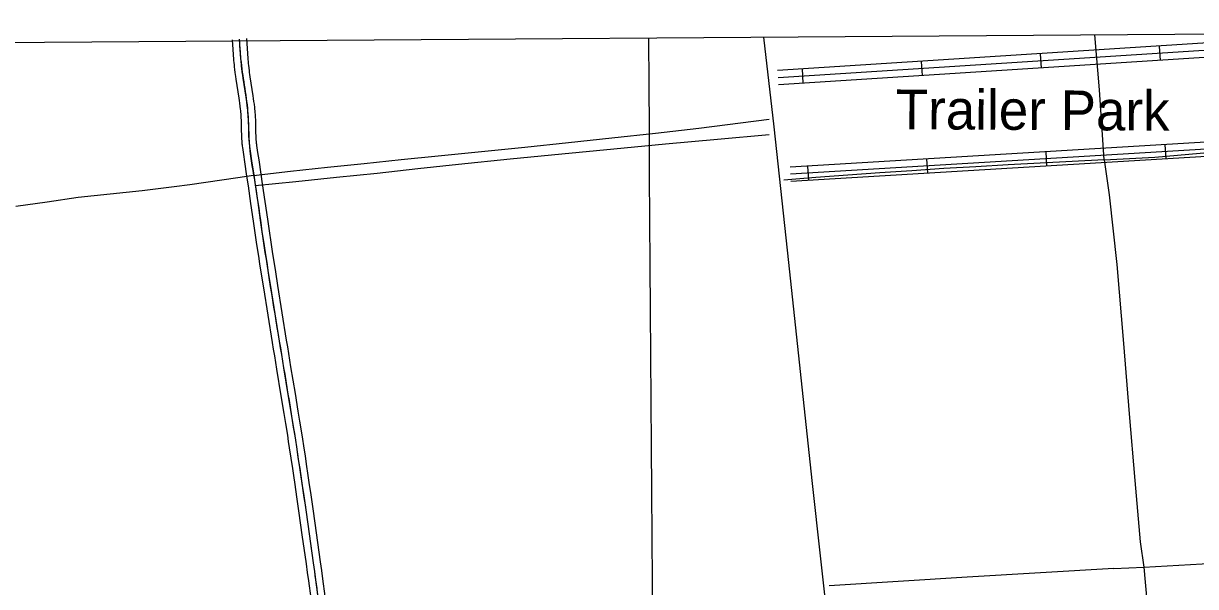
# Model space of a CAD drawing. Extents: x 3508733 to 3546731, y 546897 to 572481.
# Drawn here: x 3516762 to 3519217, y 569367 to 570545 of the extents above; entities that cross this region are included whole.
import ezdxf

# ---------------------------------------------------------------- set-up
doc = ezdxf.new("R2010")
doc.units = 0
for name, color, linetype in [('V-BLDG-IDEN', 7, 'Continuous'), ('V-DTCH-CNTR', 7, 'Continuous'), ('V-GRID-FRAM', 7, 'Continuous'), ('V-GRID-MAJR', 7, 'Continuous'), ('V-ROAD-CNTR', 7, 'Continuous'), ('V-TOPO-SHOR', 7, 'Continuous')]:
    doc.layers.add(name, color=color, linetype=linetype)

msp = doc.modelspace()

# ---------------------------------------------------------------- linework, layer by layer
at = {"layer": 'V-DTCH-CNTR'}
for points in [[(3519026.147, 570259.807), (3519015.829, 570405.975), (3519006.211868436, 570521.2976405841)], [(3517244.149, 570227.107), (3517321.3710000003, 570235.645), (3517398.613, 570243.984), (3517475.878, 570252.129), (3517553.166, 570260.073), (3517630.471, 570267.821), (3517721.577, 570276.832), (3517812.653, 570286.106), (3517903.705, 570295.6410000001), (3517994.7290000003, 570305.441), (3518085.721, 570315.501), (3518176.687, 570325.8250000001), (3518324.002, 570344.893)], [(3518324.387, 570312.191), (3518215.792, 570302.311), (3518107.215, 570292.231), (3517998.659, 570281.9500000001), (3517890.119, 570271.469), (3517781.599, 570260.784), (3517673.1010000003, 570249.899), (3517587.977, 570240.527), (3517502.8340000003, 570231.356), (3517417.668, 570222.388), (3517332.481, 570213.623), (3517247.274, 570205.06)], [(3519026.147, 570259.807), (3519132.288, 570265.251), (3519274.536, 570277.596), (3519400.435, 570284.74), (3519509.528, 570289.649), (3519634.452, 570297.794), (3519703.076, 570303.182)], [(3519026.147, 570259.807), (3518958.935, 570256.506), (3518891.736, 570252.996), (3518824.548, 570249.272), (3518757.3710000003, 570245.34), (3518690.207, 570241.1950000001), (3518623.055, 570236.843), (3518555.92, 570232.276), (3518488.798, 570227.502), (3518421.6920000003, 570222.515), (3518354.6010000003, 570217.319)], [(3519026.147, 570259.807), (3519036.4790000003, 570186.159), (3519052.73, 570040.897), (3519066.722, 569874.9450000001), (3519078.018, 569728.269), (3519090.398, 569588.487), (3519101.454, 569460.069), (3519108.699, 569407.409), (3519119.0270000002, 569297.7490000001), (3519134.738, 569149.04), (3519145.529, 569001.385), (3519159.705, 568848.752), (3519174.594, 568676.3740000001), (3519184.137, 568545.51), (3519197.224, 568385.492), (3519208.623, 568246.216), (3519211.1920000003, 568179.8690000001)], [(3517244.149, 570227.107), (3517210.857, 570221.895), (3517177.534, 570216.887), (3517144.18, 570212.085), (3517110.798, 570207.483), (3517077.389, 570203.086), (3517043.953, 570198.892), (3517010.4930000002, 570194.9), (3516977.0100000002, 570191.115), (3516943.503, 570187.533), (3516909.977, 570184.154), (3516876.429, 570180.982), (3516811.417, 570171.307), (3516746.3680000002, 570161.866)], [(3519046.498, 569404.321), (3519108.699, 569407.409), (3519231.137, 569414.108), (3519355.088, 569423.252), (3519476.623, 569435.883), (3519610.486, 569448.345), (3519731.472, 569457.036)], [(3519046.498, 569404.321), (3518738.9450000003, 569386.243), (3518450.011, 569367.838)]]:
    msp.add_lwpolyline(points, dxfattribs=at)
at = {"layer": 'V-GRID-FRAM'}
msp.add_lwpolyline([(3512799.986, 570478.871), (3544431.278, 570695.107), (3544563.5130000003, 552512.398), (3512916.353, 552296.053), (3512799.986, 570478.871)], dxfattribs=at)
at = {"layer": 'V-GRID-MAJR'}
msp.add_spline([(3518190.879, 552332.11), (3518151.221, 558391.11), (3518111.551, 564452.0430000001), (3518071.881, 570512.993), (3518071.8680000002, 570514.91)], degree=3, dxfattribs=at)
at = {"layer": 'V-ROAD-CNTR'}
for p, q in [((3519144.061673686, 570467.8630378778), (3519142.1416775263, 570497.8009780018)), ((3518645.0866716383, 570435.8711018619), (3518643.167675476, 570465.8100419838)), ((3518894.5741726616, 570451.86706987), (3518892.6541765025, 570481.8060099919)), ((3518395.5991706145, 570419.876133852), (3518393.680174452, 570449.8140739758)), ((3518906.0561496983, 570246.7004802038), (3518904.258153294, 570276.646420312)), ((3519155.606650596, 570261.683450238), (3519153.808654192, 570291.6293903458)), ((3518406.9561479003, 570216.735540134), (3518405.158151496, 570246.681480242)), ((3518656.5056488, 570231.7185101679), (3518654.707652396, 570261.664450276))]:
    msp.add_line(p, q, dxfattribs=at)
for points in [[(3519623.991713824, 570528.6939162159), (3518341.754278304, 570446.4850806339)], [(3519691.97357786, 570518.0219375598), (3518342.7142763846, 570431.5161105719)], [(3517265.371431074, 569992.0659894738), (3517260.8234401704, 570020.723932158), (3517257.444446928, 570042.235889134), (3517254.93345195, 570058.3828568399), (3517251.215459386, 570082.6048083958), (3517247.561466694, 570106.8477599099), (3517243.925473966, 570131.490710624), (3517238.5704846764, 570168.4266367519), (3517233.226495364, 570205.3275629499), (3517230.279501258, 570225.3755228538), (3517225.812510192, 570255.4734626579), (3517223.584514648, 570270.54243252), (3517221.3705190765, 570285.6714022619), (3517221.036519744, 570288.093397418), (3517220.7395203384, 570290.480392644), (3517220.4825208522, 570292.781388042), (3517220.254521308, 570295.0393835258), (3517219.891522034, 570299.283375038), (3517219.617522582, 570303.2743670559), (3517219.4145229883, 570306.988359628), (3517219.262523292, 570310.4463527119), (3517219.1475235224, 570313.6883462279), (3517218.9915238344, 570319.6533342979), (3517218.8055242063, 570329.9183137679), (3517218.6525245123, 570337.4932986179), (3517218.486524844, 570343.0722874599), (3517218.314525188, 570347.1982792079), (3517218.150525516, 570350.25727309), (3517218.007525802, 570352.5032685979), (3517217.749526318, 570355.9062617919), (3517217.4345269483, 570359.2972550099), (3517217.0855276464, 570362.5992484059), (3517216.722528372, 570365.8202419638), (3517215.951529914, 570372.1402293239), (3517215.169531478, 570378.059217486), (3517214.38853304, 570383.6272063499), (3517213.626534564, 570388.8401959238), (3517207.492546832, 570428.6721162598), (3517206.756548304, 570433.764106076), (3517206.139549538, 570438.2060971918), (3517205.616550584, 570442.12708935), (3517204.762552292, 570448.956075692), (3517204.1715534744, 570454.1220653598), (3517203.7585543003, 570458.0370575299), (3517203.207555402, 570463.853045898), (3517202.957555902, 570466.81703997), (3517202.731556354, 570469.7350341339), (3517201.21355939, 570490.445992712), (3517199.6975624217, 570511.12695135)], [(3517280.186401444, 569994.4179847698), (3517275.6394105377, 570023.06292748), (3517272.264417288, 570044.5518845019), (3517269.7574223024, 570060.67285226), (3517266.0444297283, 570084.860803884), (3517262.397437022, 570109.059755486), (3517258.7674442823, 570133.661706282), (3517253.415454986, 570170.5776324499), (3517248.069465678, 570207.4935586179), (3517245.11847158, 570227.5675184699), (3517240.6504805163, 570257.671458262), (3517238.424484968, 570272.725428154), (3517236.221489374, 570287.7823980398), (3517235.909489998, 570290.0443935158), (3517235.6364905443, 570292.2393891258), (3517235.3984910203, 570294.3673848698), (3517235.190491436, 570296.4313807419), (3517234.847492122, 570300.4363727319), (3517234.589492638, 570304.1973652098), (3517234.3964930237, 570307.7283581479), (3517234.2504933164, 570311.041351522), (3517234.140493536, 570314.150345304), (3517233.9874938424, 570319.985333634), (3517233.802494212, 570330.204313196), (3517233.64849452, 570337.86729787), (3517233.477494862, 570343.609286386), (3517233.297495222, 570347.9112777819), (3517233.1254955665, 570351.1342713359), (3517232.9714958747, 570353.549266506), (3517232.696496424, 570357.16725927), (3517232.3614970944, 570360.7792520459), (3517231.9964978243, 570364.228245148), (3517231.620498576, 570367.5672384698), (3517230.8325001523, 570374.030225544), (3517230.032501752, 570380.083213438), (3517229.2375033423, 570385.754202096), (3517228.460504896, 570391.06719147), (3517222.3285171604, 570430.8861118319), (3517221.6085186, 570435.869101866), (3517221.002519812, 570440.2310931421), (3517220.492520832, 570444.0500855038), (3517219.656522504, 570450.7390721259), (3517219.081523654, 570455.7610620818), (3517218.6845244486, 570459.5310545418), (3517218.1475255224, 570465.1920432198), (3517217.908526, 570468.0250375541), (3517217.689526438, 570470.8610318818), (3517216.17352947, 570491.5429905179), (3517214.6575325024, 570512.2239491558)], [(3517295.001371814, 569996.7699800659), (3517290.4553809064, 570025.401922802), (3517287.0843876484, 570046.86787987), (3517284.5813926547, 570062.9628476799), (3517280.8734000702, 570087.116799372), (3517277.2334073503, 570111.2717510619), (3517273.609414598, 570135.8327019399), (3517268.2604252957, 570172.7286281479), (3517262.912435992, 570209.659554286), (3517259.9574419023, 570229.7595140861), (3517255.48845084, 570259.869453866), (3517253.264455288, 570274.9084237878), (3517251.072459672, 570289.8933938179), (3517250.782460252, 570291.9953896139), (3517250.5334607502, 570293.998385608), (3517250.3144611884, 570295.9533816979), (3517250.126461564, 570297.8233779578), (3517249.80346221, 570301.5893704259), (3517249.5614626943, 570305.120363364), (3517249.3784630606, 570308.468356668), (3517249.23846334, 570311.6363503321), (3517249.1334635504, 570314.6123443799), (3517248.98346385, 570320.3173329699), (3517248.7994642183, 570330.490312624), (3517248.644464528, 570338.241297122), (3517248.4684648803, 570344.1462853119), (3517248.280465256, 570348.624276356), (3517248.100465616, 570352.0112695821), (3517247.9354659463, 570354.5952644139), (3517247.64346653, 570358.428256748), (3517247.2884672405, 570362.2612490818), (3517246.9074680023, 570365.8572418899), (3517246.51846878, 570369.3142349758), (3517245.7134703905, 570375.9202217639), (3517244.895472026, 570382.1072093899), (3517244.0864736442, 570387.8811978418), (3517243.2944752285, 570393.294187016), (3517237.1644874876, 570433.100107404), (3517236.4604888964, 570437.974097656), (3517235.8654900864, 570442.256089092), (3517235.3684910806, 570445.9730816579), (3517234.550492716, 570452.5220685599), (3517233.991493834, 570457.4000588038), (3517233.610494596, 570461.025051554), (3517233.0874956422, 570466.531040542), (3517232.859496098, 570469.2330351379), (3517232.647496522, 570471.98702963), (3517231.13349955, 570492.6399883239), (3517229.6175025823, 570513.3209469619)], [(3519692.9335759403, 570503.0529674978), (3518343.674274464, 570416.5471405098)], [(3519702.81855617, 570324.5913244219), (3518367.9512259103, 570244.44748471)], [(3519703.717554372, 570309.618354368), (3518368.850224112, 570229.4745146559)], [(3519704.616552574, 570294.6453843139), (3518369.749222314, 570214.501544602)], [(3517364.5762326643, 569342.5952884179), (3517359.7082424, 569378.335216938), (3517357.2512473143, 569396.1761812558), (3517354.754252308, 569414.016145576), (3517346.1902694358, 569474.7420241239), (3517339.749282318, 569520.276933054), (3517334.8652920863, 569554.406864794), (3517331.1562995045, 569579.987813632), (3517328.3403051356, 569599.1647752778), (3517326.207309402, 569613.537746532), (3517322.9653158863, 569635.0947034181), (3517319.667322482, 569656.6396603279), (3517317.5223267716, 569670.430632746), (3517315.484330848, 569683.3536069), (3517311.6013386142, 569707.6015584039), (3517308.155345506, 569728.8095159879), (3517302.04335773, 569765.9464417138), (3517292.82837616, 569821.6793302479), (3517288.259385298, 569849.574274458), (3517285.996389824, 569863.5362465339), (3517283.7563943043, 569877.4912186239), (3517265.375431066, 569992.0419895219)], [(3517379.43820294, 569344.625284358), (3517374.569212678, 569380.370212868), (3517372.109217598, 569398.23917713), (3517369.6082226, 569416.103141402), (3517361.04323973, 569476.840019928), (3517354.599252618, 569522.389928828), (3517349.712262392, 569556.544860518), (3517345.9992698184, 569582.1538092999), (3517343.179275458, 569601.355770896), (3517341.042279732, 569615.7537421), (3517337.7952862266, 569637.3446989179), (3517334.4922928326, 569658.9276557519), (3517332.3412971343, 569672.751628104), (3517330.29830122, 569685.707602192), (3517326.410308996, 569709.9905536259), (3517322.9583159, 569731.2305111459), (3517316.84332813, 569768.387436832), (3517307.6293465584, 569824.115325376), (3517303.064355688, 569851.986269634), (3517300.8053602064, 569865.925241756), (3517298.566364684, 569879.8682138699), (3517280.186401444, 569994.4179847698)], [(3517394.300173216, 569346.655280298), (3517389.4301829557, 569382.4052087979), (3517386.9671878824, 569400.3021730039), (3517384.462192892, 569418.190137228), (3517375.896210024, 569478.9380157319), (3517369.449222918, 569524.502924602), (3517364.559232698, 569558.6828562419), (3517360.8422401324, 569584.3198049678), (3517358.01824578, 569603.5467665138), (3517355.877250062, 569617.9697376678), (3517352.6252565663, 569639.594694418), (3517349.3172631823, 569661.2156511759), (3517347.160267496, 569675.072623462), (3517345.112271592, 569688.0615974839), (3517341.219279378, 569712.3795488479), (3517337.761286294, 569733.651506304), (3517331.64329853, 569770.8284319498), (3517322.4303169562, 569826.5513205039), (3517317.8693260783, 569854.3982648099), (3517315.6143305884, 569868.3142369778), (3517313.376335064, 569882.245209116), (3517294.9973718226, 569996.7939800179)]]:
    msp.add_lwpolyline(points, dxfattribs=at)
msp.add_spline([(3518521.097919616, 568161.867649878), (3518476.2020094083, 568160.5396525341), (3518343.213275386, 568156.6056604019), (3518234.7574922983, 568152.6686682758), (3518103.5127547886, 568139.0706954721), (3517970.860020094, 568131.9897096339), (3517852.533256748, 568125.0887234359), (3517723.7565143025, 568118.3647368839), (3517607.51274679, 568114.925743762), (3517582.380797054, 568118.797736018), (3517561.9568379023, 568135.9237017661), (3517552.0888576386, 568157.492658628), (3517542.5248767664, 568216.7205401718), (3517513.4509349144, 568461.907049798), (3517473.805014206, 568734.7165041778), (3517430.5471007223, 569006.446960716), (3517389.360183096, 569273.867425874), (3517369.6082226, 569416.103141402), (3517334.4922928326, 569658.9276557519), (3517298.566364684, 569879.8682138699), (3517262.397437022, 570109.059755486), (3517248.069465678, 570207.4935586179), (3517236.221489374, 570287.7823980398), (3517232.3614970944, 570360.7792520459), (3517217.689526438, 570470.8610318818), (3517214.6575325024, 570512.2239491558)], degree=3, dxfattribs=at)
at = {"layer": 'V-TOPO-SHOR'}
msp.add_lwpolyline([(3518574.6920000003, 568126.828), (3518548.784, 568347.115), (3518506.02, 568755.987), (3518449.522, 569266.632), (3518414.444, 569588.372), (3518365.107, 570044.474), (3518334.801, 570328.434), (3518313.328648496, 570516.5609925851)], dxfattribs=at)

# ---------------------------------------------------------------- texts
at = {"layer": 'V-BLDG-IDEN'}
msp.add_text('Trailer Park', height=82.99983200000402, rotation=359.6701050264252, dxfattribs=at).set_placement((3518589.1937834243, 570323.944325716))

doc.saveas('drawing.dxf')
